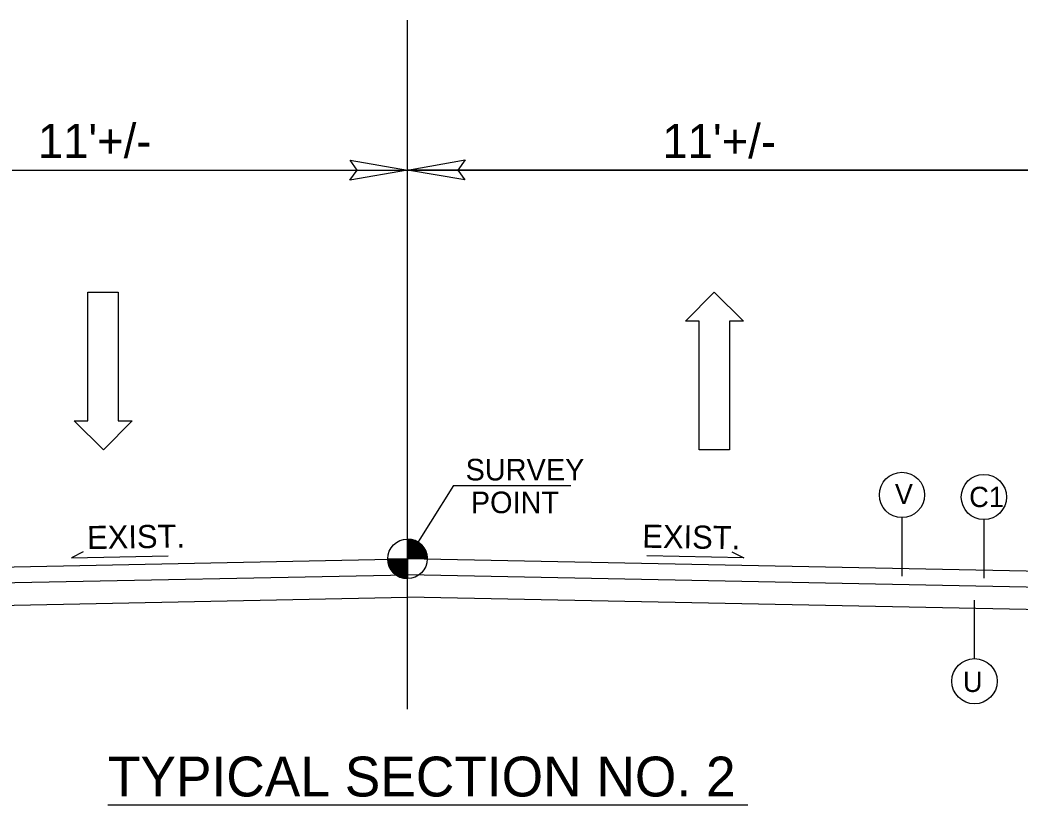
# Model space of a CAD drawing. Extents: x 1022283 to 1026986, y 174822 to 180471.
# Drawn here: x 1023625.2 to 1024095.7, y 179399.4 to 179768.7 of the extents above; entities that cross this region are included whole.
import ezdxf

# ---------------------------------------------------------------- set-up
doc = ezdxf.new("R2010")
doc.units = 0
for name, color, linetype in [('Default', 7, 'Continuous'), ('Prop Dimension', 7, 'Continuous'), ('Prop Lane Arrow CELL', 7, 'Continuous'), ('Prop Terminator CELL', 7, 'Continuous'), ('Typical Berm Information CELL', 7, 'Continuous'), ('Typical Grade Point Symbol CELL', 7, 'Continuous'), ('Typical ID Circle CELL', 7, 'Continuous'), ('Typical Text Grade Point CELL', 7, 'Continuous'), ('Typical Text ID Circle CELL', 7, 'Continuous'), ('Typical Text Label CELL', 7, 'Continuous')]:
    doc.layers.add(name, color=color, linetype=linetype)

# ---------------------------------------------------------------- blocks, each defined once
blk = doc.blocks.new('Lane Arrow Through')
at = {"layer": 'Prop Lane Arrow CELL'}
for p, q in [((-3.15, 1.6), (-3.15, 3.1)), ((-3.15, 3.1), (0, 0)), ((-17.15, 1.6), (-3.15, 1.6)), ((-17.15, -1.7), (-17.15, 1.6)), ((0, 0), (-3.15, -3.2)), ((-3.15, -1.7), (-17.15, -1.7)), ((-3.15, -3.2), (-3.15, -1.7))]:
    blk.add_line(p, q, dxfattribs=at)

msp = doc.modelspace()

# ---------------------------------------------------------------- linework, layer by layer
at = {"layer": 'Default'}
for p, q in [((1023299.79, 179698.14), (1023807.5, 179698.14)), ((1023807.5, 179698.14), (1024315.21, 179698.14)), ((1024315.21, 179698.14), (1023807.5, 179698.14))]:
    msp.add_line(p, q, dxfattribs=at)
at = {"layer": 'Prop Dimension'}
for p, q in [((1023807.5, 179709.25), (1023807.5, 179768.7)), ((1023807.5, 179444.45), (1023807.5, 179709.25)), ((1023829.15, 179549.68), (1023807.5, 179515.24)), ((1023829.15, 179549.68), (1023807.5, 179515.24)), ((1023299.79, 179505.09), (1023807.5, 179515.24)), ((1023299.79, 179505.09), (1023807.5, 179515.24)), ((1024315.21, 179505.09), (1023807.5, 179515.24)), ((1024315.21, 179505.09), (1023807.5, 179515.24)), ((1023299.79, 179497.58), (1023807.5, 179507.74)), ((1023299.79, 179497.58), (1023807.5, 179507.74)), ((1024315.21, 179497.58), (1023807.5, 179507.74)), ((1024315.21, 179497.58), (1023807.5, 179507.74)), ((1023299.79, 179487), (1023807.5, 179497.16)), ((1024315.21, 179487), (1023807.5, 179497.16))]:
    msp.add_line(p, q, dxfattribs=at)
at = {"layer": 'Prop Terminator CELL'}
for points in [[(1023780.5, 179702.79), (1023807.5, 179698.14), (1023780.35, 179693.34), (1023783.8, 179698.14)], [(1023834.5, 179693.49), (1023807.5, 179698.14), (1023834.65, 179702.94), (1023831.2, 179698.14)], [(1023834.5, 179693.49), (1023807.5, 179698.14), (1023834.65, 179702.94), (1023831.2, 179698.14)]]:
    msp.add_lwpolyline(points, close=True, dxfattribs=at)
at = {"layer": 'Typical Berm Information CELL'}
for p, q in [((1023654.85, 179518.45), (1023649.33, 179515.69)), ((1023649.33, 179515.69), (1023694.85, 179516.6)), ((1023965.68, 179515.69), (1023920.16, 179516.6)), ((1023960.16, 179518.45), (1023965.68, 179515.69))]:
    msp.add_line(p, q, dxfattribs=at)
at = {"layer": 'Typical Grade Point Symbol CELL'}
for p, q in [((1023807.5, 179515.24), (1023807.5, 179524.54)), ((1023807.5, 179515.24), (1023807.5, 179524.54)), ((1023798.21, 179515.24), (1023807.5, 179515.24)), ((1023798.21, 179515.24), (1023807.5, 179515.24)), ((1023807.48, 179505.95), (1023807.5, 179515.24)), ((1023807.5, 179515.24), (1023807.48, 179505.95)), ((1023807.48, 179505.95), (1023807.5, 179515.24)), ((1023807.5, 179515.24), (1023807.48, 179505.95)), ((1023816.8, 179515.24), (1023807.5, 179515.24)), ((1023816.8, 179515.24), (1023807.5, 179515.24))]:
    msp.add_line(p, q, dxfattribs=at)
for points in [[(1023807.59, 179524.54), (1023807.59, 179524.54), (1023807.59, 179515.24)], [(1023807.59, 179524.54), (1023807.59, 179524.54), (1023807.59, 179515.24)], [(1023807.77, 179524.54), (1023807.77, 179515.24)], [(1023807.77, 179524.54), (1023807.77, 179515.24)], [(1023807.96, 179524.52), (1023807.96, 179515.24)], [(1023807.96, 179524.52), (1023807.96, 179515.24)], [(1023808.14, 179524.52), (1023808.14, 179515.24)], [(1023808.14, 179524.52), (1023808.14, 179515.24)], [(1023808.33, 179524.49), (1023808.33, 179515.24)], [(1023808.33, 179524.49), (1023808.33, 179515.24)], [(1023808.52, 179524.47), (1023808.52, 179515.24)], [(1023808.52, 179524.47), (1023808.52, 179515.24)], [(1023808.7, 179524.45), (1023808.7, 179515.24)], [(1023808.7, 179524.45), (1023808.7, 179515.24)], [(1023808.89, 179524.43), (1023808.89, 179515.24)], [(1023808.89, 179524.43), (1023808.89, 179515.24)], [(1023809.07, 179524.41), (1023809.07, 179515.24)], [(1023809.07, 179524.41), (1023809.07, 179515.24)], [(1023809.26, 179524.37), (1023809.26, 179515.24)], [(1023809.26, 179524.37), (1023809.26, 179515.24)], [(1023809.45, 179524.33), (1023809.45, 179515.24)], [(1023809.45, 179524.33), (1023809.45, 179515.24)], [(1023809.63, 179524.29), (1023809.63, 179515.24)], [(1023809.63, 179524.29), (1023809.63, 179515.24)], [(1023809.82, 179524.25), (1023809.82, 179515.24)], [(1023809.82, 179524.25), (1023809.82, 179515.24)], [(1023810, 179524.19), (1023810, 179515.24)], [(1023810, 179524.19), (1023810, 179515.24)], [(1023810.19, 179524.14), (1023810.19, 179515.24)], [(1023810.19, 179524.14), (1023810.19, 179515.24)], [(1023810.38, 179524.08), (1023810.38, 179515.24)], [(1023810.38, 179524.08), (1023810.38, 179515.24)], [(1023810.56, 179524.02), (1023810.56, 179515.24)], [(1023810.56, 179524.02), (1023810.56, 179515.24)], [(1023810.75, 179523.96), (1023810.75, 179515.24)], [(1023810.75, 179523.96), (1023810.75, 179515.24)], [(1023810.93, 179523.87), (1023810.93, 179515.24)], [(1023810.93, 179523.87), (1023810.93, 179515.24)], [(1023811.12, 179523.79), (1023811.12, 179515.24)], [(1023811.12, 179523.79), (1023811.12, 179515.24)], [(1023811.31, 179523.71), (1023811.31, 179515.24)], [(1023811.31, 179523.71), (1023811.31, 179515.24)], [(1023811.49, 179523.63), (1023811.49, 179515.24)], [(1023811.49, 179523.63), (1023811.49, 179515.24)], [(1023811.68, 179523.54), (1023811.68, 179515.24)], [(1023811.68, 179523.54), (1023811.68, 179515.24)], [(1023811.86, 179523.44), (1023811.86, 179515.24)], [(1023811.86, 179523.44), (1023811.86, 179515.24)], [(1023812.05, 179523.34), (1023812.05, 179515.24)], [(1023812.05, 179523.34), (1023812.05, 179515.24)], [(1023812.23, 179523.23), (1023812.23, 179515.24)], [(1023812.23, 179523.23), (1023812.23, 179515.24)], [(1023812.42, 179523.13), (1023812.42, 179515.24)], [(1023812.42, 179523.13), (1023812.42, 179515.24)], [(1023812.61, 179523.01), (1023812.61, 179515.24)], [(1023812.61, 179523.01), (1023812.61, 179515.24)], [(1023812.79, 179522.88), (1023812.79, 179515.24)], [(1023812.79, 179522.88), (1023812.79, 179515.24)], [(1023812.98, 179522.74), (1023812.98, 179515.24)], [(1023812.98, 179522.74), (1023812.98, 179515.24)], [(1023813.16, 179522.61), (1023813.16, 179515.24)], [(1023813.16, 179522.61), (1023813.16, 179515.24)], [(1023813.35, 179522.47), (1023813.35, 179515.24)], [(1023813.35, 179522.47), (1023813.35, 179515.24)], [(1023813.54, 179522.31), (1023813.54, 179515.24)], [(1023813.54, 179522.31), (1023813.54, 179515.24)], [(1023813.72, 179522.14), (1023813.72, 179515.24)], [(1023813.72, 179522.14), (1023813.72, 179515.24)], [(1023813.91, 179521.97), (1023813.91, 179515.24)], [(1023813.91, 179521.97), (1023813.91, 179515.24)], [(1023814.09, 179521.79), (1023814.09, 179515.24)], [(1023814.09, 179521.79), (1023814.09, 179515.24)], [(1023814.28, 179521.6), (1023814.28, 179515.24)], [(1023814.28, 179521.6), (1023814.28, 179515.24)], [(1023814.47, 179521.4), (1023814.47, 179515.24)], [(1023814.47, 179521.4), (1023814.47, 179515.24)], [(1023814.65, 179521.17), (1023814.65, 179515.24)], [(1023814.65, 179521.17), (1023814.65, 179515.24)], [(1023814.84, 179520.94), (1023814.84, 179515.24)], [(1023814.84, 179520.94), (1023814.84, 179515.24)], [(1023815.02, 179520.69), (1023815.02, 179515.24)], [(1023815.02, 179520.69), (1023815.02, 179515.24)], [(1023815.21, 179520.42), (1023815.21, 179515.24)], [(1023815.21, 179520.42), (1023815.21, 179515.24)], [(1023815.4, 179520.14), (1023815.4, 179515.24)], [(1023815.4, 179520.14), (1023815.4, 179515.24)], [(1023815.58, 179519.83), (1023815.58, 179515.24)], [(1023815.58, 179519.83), (1023815.58, 179515.24)], [(1023815.77, 179519.5), (1023815.77, 179515.24)], [(1023815.77, 179519.5), (1023815.77, 179515.24)], [(1023798.25, 179515.24), (1023798.25, 179514.23)], [(1023798.25, 179515.24), (1023798.25, 179514.23)], [(1023798.44, 179515.24), (1023798.44, 179513.13)], [(1023798.44, 179515.24), (1023798.44, 179513.13)], [(1023798.62, 179515.24), (1023798.62, 179512.47)], [(1023798.62, 179515.24), (1023798.62, 179512.47)], [(1023798.81, 179515.24), (1023798.81, 179511.91)], [(1023798.81, 179515.24), (1023798.81, 179511.91)], [(1023798.99, 179515.24), (1023798.99, 179511.48)], [(1023798.99, 179515.24), (1023798.99, 179511.48)], [(1023799.18, 179515.24), (1023799.18, 179511.09)], [(1023799.18, 179515.24), (1023799.18, 179511.09)], [(1023799.37, 179515.24), (1023799.37, 179510.74)], [(1023799.37, 179515.24), (1023799.37, 179510.74)], [(1023799.55, 179515.24), (1023799.55, 179510.41)], [(1023799.55, 179515.24), (1023799.55, 179510.41)], [(1023799.74, 179515.24), (1023799.74, 179510.12)], [(1023799.74, 179515.24), (1023799.74, 179510.12)], [(1023799.92, 179515.24), (1023799.92, 179509.85)], [(1023799.92, 179515.24), (1023799.92, 179509.85)], [(1023800.11, 179515.24), (1023800.11, 179509.6)], [(1023800.11, 179515.24), (1023800.11, 179509.6)], [(1023800.3, 179515.24), (1023800.3, 179509.37)], [(1023800.3, 179515.24), (1023800.3, 179509.37)], [(1023800.48, 179515.24), (1023800.48, 179509.15)], [(1023800.48, 179515.24), (1023800.48, 179509.15)], [(1023800.67, 179515.24), (1023800.67, 179508.94)], [(1023800.67, 179515.24), (1023800.67, 179508.94)], [(1023800.85, 179515.24), (1023800.85, 179508.73)], [(1023800.85, 179515.24), (1023800.85, 179508.73)], [(1023801.04, 179515.24), (1023801.04, 179508.55)], [(1023801.04, 179515.24), (1023801.04, 179508.55)], [(1023801.23, 179515.24), (1023801.23, 179508.38)], [(1023801.23, 179515.24), (1023801.23, 179508.38)], [(1023801.41, 179515.24), (1023801.41, 179508.22)], [(1023801.41, 179515.24), (1023801.41, 179508.22)], [(1023801.6, 179515.24), (1023801.6, 179508.05)], [(1023801.6, 179515.24), (1023801.6, 179508.05)], [(1023801.78, 179515.24), (1023801.78, 179507.91)], [(1023801.78, 179515.24), (1023801.78, 179507.91)], [(1023801.97, 179515.24), (1023801.97, 179507.76)], [(1023801.97, 179515.24), (1023801.97, 179507.76)], [(1023802.15, 179515.24), (1023802.15, 179507.64)], [(1023802.15, 179515.24), (1023802.15, 179507.64)], [(1023802.34, 179515.24), (1023802.34, 179507.52)], [(1023802.34, 179515.24), (1023802.34, 179507.52)], [(1023802.53, 179515.24), (1023802.53, 179507.39)], [(1023802.53, 179515.24), (1023802.53, 179507.39)], [(1023802.71, 179515.24), (1023802.71, 179507.27)], [(1023802.71, 179515.24), (1023802.71, 179507.27)], [(1023802.9, 179515.24), (1023802.9, 179507.16)], [(1023802.9, 179515.24), (1023802.9, 179507.16)], [(1023803.08, 179515.24), (1023803.08, 179507.06)], [(1023803.08, 179515.24), (1023803.08, 179507.06)], [(1023803.27, 179515.24), (1023803.27, 179506.96)], [(1023803.27, 179515.24), (1023803.27, 179506.96)], [(1023803.46, 179515.24), (1023803.46, 179506.88)], [(1023803.46, 179515.24), (1023803.46, 179506.88)], [(1023803.64, 179515.24), (1023803.64, 179506.79)], [(1023803.64, 179515.24), (1023803.64, 179506.79)], [(1023803.83, 179515.24), (1023803.83, 179506.71)], [(1023803.83, 179515.24), (1023803.83, 179506.71)], [(1023804.01, 179515.24), (1023804.01, 179506.63)], [(1023804.01, 179515.24), (1023804.01, 179506.63)], [(1023804.2, 179515.24), (1023804.2, 179506.54)], [(1023804.2, 179515.24), (1023804.2, 179506.54)], [(1023804.39, 179515.24), (1023804.39, 179506.48)], [(1023804.39, 179515.24), (1023804.39, 179506.48)], [(1023804.57, 179515.24), (1023804.57, 179506.42)], [(1023804.57, 179515.24), (1023804.57, 179506.42)], [(1023804.76, 179515.24), (1023804.76, 179506.36)], [(1023804.76, 179515.24), (1023804.76, 179506.36)], [(1023804.94, 179515.24), (1023804.94, 179506.32)], [(1023804.94, 179515.24), (1023804.94, 179506.32)], [(1023805.13, 179515.24), (1023805.13, 179506.26)], [(1023805.13, 179515.24), (1023805.13, 179506.26)], [(1023805.32, 179515.24), (1023805.32, 179506.21)], [(1023805.32, 179515.24), (1023805.32, 179506.21)], [(1023805.5, 179515.24), (1023805.5, 179506.17)], [(1023805.5, 179515.24), (1023805.5, 179506.17)], [(1023805.69, 179515.24), (1023805.69, 179506.13)], [(1023805.69, 179515.24), (1023805.69, 179506.13)], [(1023805.87, 179515.24), (1023805.87, 179506.09)], [(1023805.87, 179515.24), (1023805.87, 179506.09)], [(1023806.06, 179515.24), (1023806.06, 179506.07)], [(1023806.06, 179515.24), (1023806.06, 179506.07)], [(1023806.24, 179515.24), (1023806.24, 179506.03)], [(1023806.24, 179515.24), (1023806.24, 179506.03)], [(1023806.43, 179515.24), (1023806.43, 179506.01)], [(1023806.43, 179515.24), (1023806.43, 179506.01)], [(1023806.62, 179515.24), (1023806.62, 179505.99)], [(1023806.62, 179515.24), (1023806.62, 179505.99)], [(1023806.8, 179515.24), (1023806.8, 179505.97)], [(1023806.8, 179515.24), (1023806.8, 179505.97)], [(1023806.99, 179515.24), (1023806.99, 179505.97)], [(1023806.99, 179515.24), (1023806.99, 179505.97)], [(1023807.17, 179515.24), (1023807.17, 179505.95)], [(1023807.17, 179515.24), (1023807.17, 179505.95)], [(1023807.36, 179515.24), (1023807.36, 179505.95), (1023807.36, 179505.95)], [(1023807.36, 179515.24), (1023807.36, 179505.95), (1023807.36, 179505.95)], [(1023815.95, 179519.1), (1023815.95, 179515.24)], [(1023815.95, 179519.1), (1023815.95, 179515.24)], [(1023816.14, 179518.67), (1023816.14, 179515.24)], [(1023816.14, 179518.67), (1023816.14, 179515.24)], [(1023816.32, 179518.15), (1023816.32, 179515.24)], [(1023816.32, 179518.15), (1023816.32, 179515.24)], [(1023816.51, 179517.51), (1023816.51, 179515.24)], [(1023816.51, 179517.51), (1023816.51, 179515.24)], [(1023816.7, 179516.56), (1023816.7, 179515.24)], [(1023816.7, 179516.56), (1023816.7, 179515.24)]]:
    msp.add_lwpolyline(points, dxfattribs=at)
msp.add_circle((1023807.49, 179515.24), 9.3, dxfattribs=at)
msp.add_circle((1023807.49, 179515.24), 9.3, dxfattribs=at)
for start, end in [(359.9905, 89.9905), (359.9905, 89.9905), (179.9905, 269.9905), (179.9905, 269.9905)]:
    msp.add_arc((1023807.49, 179515.24), 9.3, start, end, dxfattribs=at)
at = {"layer": 'Typical ID Circle CELL'}
for p, q in [((1024040.15, 179534.64), (1024040.15, 179507.11)), ((1024078.68, 179533.67), (1024078.68, 179506.15)), ((1024074.27, 179468.31), (1024074.27, 179495.84))]:
    msp.add_line(p, q, dxfattribs=at)
for centre in [(1024040.15, 179545.28), (1024078.68, 179544.32), (1024074.27, 179457.66)]:
    msp.add_circle(centre, 10.65, dxfattribs=at)
at = {"layer": 'Typical Text Grade Point CELL'}
msp.add_line((1023829.15, 179549.68), (1023884.26, 179549.68), dxfattribs=at)
at = {"layer": 'Typical Text Label CELL'}
msp.add_line((1023666.49, 179399.44), (1023967.65, 179399.44), dxfattribs=at)

# ---------------------------------------------------------------- block references
at = {"layer": 'Prop Lane Arrow CELL', "xscale": 4.329849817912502}
for p, yscale, rotation in [((1023664.46, 179566.45), 4.3298498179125, -89.99999999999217), ((1023951.7, 179640.7), 4.329849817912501, 90.00000000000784), ((1023951.7, 179640.7), 4.329849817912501, 90.00000000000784)]:
    msp.add_blockref('Lane Arrow Through', p, dxfattribs=dict(at, yscale=yscale, rotation=rotation))

# ---------------------------------------------------------------- texts
at = {"layer": 'Prop Dimension'}
for p in [(1023633.57, 179703.85), (1023927.42, 179703.73)]:
    msp.add_text("11'+/-", height=16, dxfattribs=at).set_placement(p)
at = {"layer": 'Typical Berm Information CELL'}
for rotation, p in [(0.9927, (1023656.82, 179519.79)), (359.0073, (1023917.9, 179520.49))]:
    msp.add_text('EXIST.', height=10.873, rotation=rotation, dxfattribs=at).set_placement(p)
at = {"layer": 'Typical Text Grade Point CELL'}
for s, p in [('SURVEY', (1023834.82, 179552.11)), ('POINT', (1023837.27, 179536.71))]:
    msp.add_text(s, height=10.163, dxfattribs=at).set_placement(p)
at = {"layer": 'Typical Text ID Circle CELL'}
for s, height, p in [('V', 9.53, (1024036.8, 179540.98)), ('C1', 9.534, (1024071.79, 179539.59)), ('U', 9.53, (1024068.82, 179452.6))]:
    msp.add_text(s, height=height, dxfattribs=at).set_placement(p)
at = {"layer": 'Typical Text Label CELL'}
msp.add_text('TYPICAL SECTION NO. 2', height=18.75, dxfattribs=at).set_placement((1023666.49, 179403.44))

doc.saveas('drawing.dxf')
